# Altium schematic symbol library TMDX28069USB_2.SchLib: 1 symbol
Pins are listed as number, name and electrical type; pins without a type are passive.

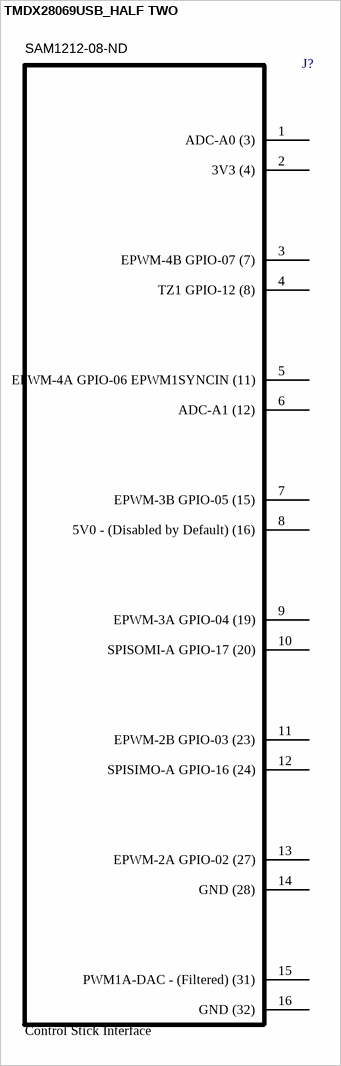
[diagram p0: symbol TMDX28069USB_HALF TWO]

## TMDX28069USB_HALF TWO
designator J?  Name: Control Stick Interface  Supplier Part Number: SAM1212-08-ND  (hidden comment: *)
DEV STICK USB PICCOLO F28069 HALF PART; PartNumber: SSW-108-01-T-D; Description: SOCKET FOR PICCOLO F28069; Board Type: Evaluation Platform; Contents: Board(s)
footprint Samtec_SSW-108-01-x-D (Receptacle, 2.54mm, 8x2, TH)
pins: 1 ADC-A0 (3), 2 3V3 (4), 3 EPWM-4B GPIO-07 (7), 4 TZ1 GPIO-12 (8), 5 EPWM-4A GPIO-06 EPWM1SYNCIN (11), 6 ADC-A1 (12), 7 EPWM-3B GPIO-05 (15), 8 5V0 - (Disabled by Default) (16), 9 EPWM-3A GPIO-04 (19), 10 SPISOMI-A GPIO-17 (20), 11 EPWM-2B GPIO-03 (23), 12 SPISIMO-A GPIO-16 (24), 13 EPWM-2A GPIO-02 (27), 14 GND (28), 15 PWM1A-DAC - (Filtered) (31), 16 GND (32)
